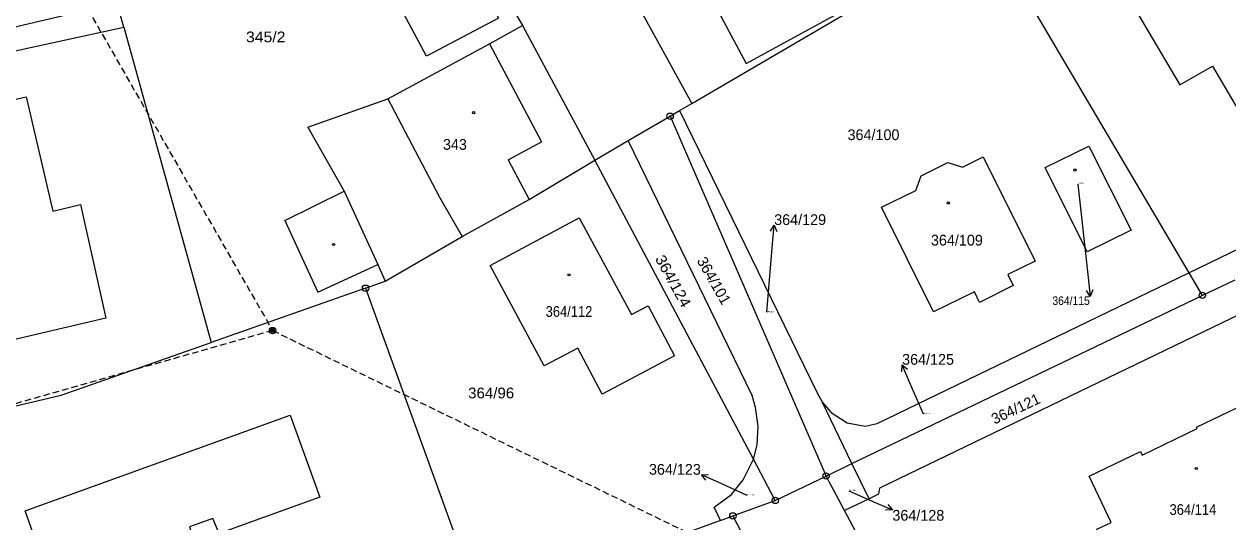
# Model space of a CAD drawing. Extents: x -592965 to -592390, y -1145071 to -1144631.
# Drawn here: x -592689.4 to -592594.1, y -1144977 to -1144937.6 of the extents above; entities that cross this region are included whole.
import ezdxf

# ---------------------------------------------------------------- set-up
doc = ezdxf.new("R2010")
doc.units = 0
doc.header["$LTSCALE"] = 0.17
doc.linetypes.add('MEDIUM_DASHED', pattern=[4.5, 3, -1.5])
doc.layers.add('4', color=7, linetype='Continuous', lineweight=25)

msp = doc.modelspace()

# ---------------------------------------------------------------- linework, layer by layer
at = {"layer": '4'}
for p, q in [((-592657.03, -1144925.29), (-592649.94, -1144937.68)), ((-592636.52, -1144943.86), (-592613.14, -1144930.18)), ((-592643.64, -1144930.93), (-592636.52, -1144943.86)), ((-592681.5, -1144937.82), (-592674.57, -1144962.77)), ((-592652.54, -1144939.13), (-592649.94, -1144937.68)), ((-592649.94, -1144937.68), (-592644.2, -1144948.33)), ((-592660.6, -1144943.48), (-592652.54, -1144939.13)), ((-592666.92, -1144945.72), (-592660.6, -1144943.48)), ((-592638.24, -1144944.86), (-592625.89, -1144973.34)), ((-592666.92, -1144945.72), (-592664.06, -1144950.8)), ((-592668.76, -1144953.11), (-592664.06, -1144950.8)), ((-592668.76, -1144953.11), (-592666.13, -1144958.79)), ((-592666.13, -1144958.79), (-592661.38, -1144956.59)), ((-592661.38, -1144956.59), (-592660.8, -1144957.92)), ((-592596.1, -1144959.04), (-592593.51, -1144957.8)), ((-592662.36, -1144958.47), (-592674.57, -1144962.77)), ((-592662.36, -1144958.47), (-592660.8, -1144957.92)), ((-592662.36, -1144958.47), (-592653.19, -1144983.74)), ((-592686.45, -1144966.95), (-592674.57, -1144962.77)), ((-592703.18, -1144970.84), (-592686.45, -1144966.95)), ((-592629.91, -1144975.27), (-592625.89, -1144973.34)), ((-592633.27, -1144976.49), (-592629.91, -1144975.27)), ((-592634.25, -1144976.85), (-592649.43, -1144982.37)), ((-592634.25, -1144976.85), (-592633.27, -1144976.49)), ((-592618.23, -1145004.75), (-592633.27, -1144976.49))]:
    msp.add_line(p, q, dxfattribs=at)
at = {"layer": '4', "lineweight": 13}
for p, q in [((-592636.53, -1144932.59), (-592632.22, -1144940.68)), ((-592632.22, -1144940.68), (-592624.61, -1144936.54)), ((-592652.54, -1144939.13), (-592648.42, -1144946.9)), ((-592660.6, -1144943.48), (-592656.51, -1144951.26)), ((-592651.07, -1144948.31), (-592648.42, -1144946.9)), ((-592651.07, -1144948.31), (-592649.4, -1144951.44)), ((-592664.06, -1144950.8), (-592661.38, -1144956.59)), ((-592656.51, -1144951.26), (-592654.71, -1144954.39))]:
    msp.add_line(p, q, dxfattribs=at)
at = {"layer": '4', "linetype": 'MEDIUM_DASHED'}
for points in [[(-592857.7, -1144647.96), (-592827.25, -1144698.04), (-592798.73, -1144745.3), (-592765.1, -1144800.74), (-592721.92, -1144873.86), (-592693.51, -1144920.47), (-592669.72, -1144961.82), (-592709.34, -1144973.09), (-592761.29, -1144989.89), (-592825.83, -1145034.08), (-592878.88, -1145071.17)], [(-592669.72, -1144961.82), (-592599.07, -1144996.19), (-592537.81, -1145025.68), (-592483.65, -1145051.69)]]:
    msp.add_lwpolyline(points, dxfattribs=at)
at = {"layer": '4'}
for points in [[(-592601.13, -1144936.9), (-592597.88, -1144942.39), (-592595.3, -1144940.9), (-592592.02, -1144946.46), (-592584.34, -1144941.94), (-592587.57, -1144936.44), (-592582.29, -1144933.34), (-592585.64, -1144927.65)], [(-592661.27, -1144933.1), (-592655.56, -1144930.04), (-592651.84, -1144937.11), (-592657.53, -1144940.1)], [(-592682.91, -1144960.84), (-592695.32, -1144963.74), (-592697.38, -1144954.72), (-592695.57, -1144954.34), (-592697.68, -1144945.28), (-592689.24, -1144943.33), (-592687.12, -1144952.37), (-592684.94, -1144951.85)], [(-592601.74, -1144953.89), (-592605.21, -1144955.59), (-592608.54, -1144948.93), (-592605.08, -1144947.23)], [(-592621.5, -1144952.06), (-592618.78, -1144950.73), (-592618.37, -1144949.58), (-592616.25, -1144948.52), (-592615.1, -1144948.89), (-592613.45, -1144948.07), (-592609.34, -1144956.33), (-592611.5, -1144957.4), (-592611.08, -1144958.26), (-592613.74, -1144959.6), (-592614.15, -1144958.75), (-592617.38, -1144960.33)], [(-592652.49, -1144956.68), (-592645.43, -1144952.89), (-592641.31, -1144960.55), (-592639.98, -1144959.87), (-592637.9, -1144963.82), (-592643.62, -1144966.87), (-592645.54, -1144963.21), (-592648.21, -1144964.61)], [(-592601.78, -1144983.1), (-592604.44, -1144977.55), (-592603.32, -1144977.01), (-592605.06, -1144973.35), (-592601, -1144971.39), (-592600.86, -1144971.68), (-592596.51, -1144969.57), (-592596.55, -1144969.48), (-592592.72, -1144967.63), (-592588.6, -1144976.22), (-592592.06, -1144977.86), (-592590.98, -1144980.12), (-592596.32, -1144982.68), (-592596.19, -1144982.99), (-592599.54, -1144984.65), (-592600.66, -1144982.55)], [(-592689.32, -1144976.1), (-592668.32, -1144968.52), (-592665.99, -1144975.02), (-592673.94, -1144977.88), (-592674.44, -1144976.7), (-592676.29, -1144977.37), (-592673.71, -1144984.65), (-592681.27, -1144987.36), (-592683.04, -1144982.4), (-592686.63, -1144983.68)]]:
    msp.add_lwpolyline(points, close=True, dxfattribs=at)
for points in [[(-592613.14, -1144930.18), (-592597.16, -1144957.25), (-592596.1, -1144959.04)], [(-592709.85, -1144942.41), (-592686.06, -1144936.85), (-592682.2, -1144935.31)], [(-592709.5, -1144943.92), (-592681.5, -1144937.82), (-592682.2, -1144935.31)], [(-592637.49, -1144944.42), (-592626.62, -1144966.7), (-592626.18, -1144967.53), (-592625.48, -1144968.32), (-592624.23, -1144969.12), (-592622.8, -1144969.4), (-592621.85, -1144969.17), (-592597.16, -1144957.25), (-592570.98, -1144944.6), (-592559.91, -1144939.25)], [(-592557.84, -1144942.95), (-592559.8, -1144944.02), (-592559.63, -1144944.38), (-592592.29, -1144960.13), (-592621.67, -1144974.31), (-592621.74, -1144974.77), (-592622.49, -1144975.13), (-592624.43, -1144976.07)], [(-592644.2, -1144948.33), (-592641.55, -1144946.78), (-592638.24, -1144944.86), (-592637.49, -1144944.42), (-592636.52, -1144943.86)], [(-592634.25, -1144976.85), (-592634.75, -1144975.81), (-592633.39, -1144974.79), (-592632.45, -1144973.64), (-592631.65, -1144972), (-592631.35, -1144970.88), (-592631.28, -1144969.38), (-592631.48, -1144967.91), (-592631.74, -1144966.96), (-592641.55, -1144946.78)], [(-592660.8, -1144957.92), (-592654.71, -1144954.39), (-592649.4, -1144951.44), (-592644.2, -1144948.33)], [(-592629.91, -1144975.27), (-592631.65, -1144972), (-592644.2, -1144948.33)], [(-592625.89, -1144973.34), (-592623.84, -1144972.35), (-592596.1, -1144959.04)], [(-592622.49, -1144975.13), (-592623.84, -1144972.35), (-592626.18, -1144967.53)], [(-592625.89, -1144973.34), (-592625.69, -1144973.71), (-592624.75, -1144975.48)], [(-592611.32, -1145000.71), (-592624.43, -1144976.07), (-592624.75, -1144975.48)]]:
    msp.add_lwpolyline(points, dxfattribs=at)
at = {"layer": '4', "lineweight": 13}
for points in [[(-592605.95, -1144950.23), (-592605.134, -1144957.629), (-592604.97, -1144959.12)], [(-592630.57, -1144960.37), (-592630.124, -1144954.965), (-592630.001, -1144953.47)], [(-592630.291, -1144953.948), (-592630.001, -1144953.47), (-592629.793, -1144953.989)], [(-592604.776, -1144958.596), (-592604.97, -1144959.12), (-592605.273, -1144958.65)], [(-592619.901, -1144965.088), (-592619.871, -1144964.53), (-592619.443, -1144964.888)], [(-592618.17, -1144968.44), (-592619.273, -1144965.905), (-592619.871, -1144964.53)], [(-592635.408, -1144973.669), (-592635.76, -1144973.235), (-592635.202, -1144973.214)], [(-592632.15, -1144974.87), (-592634.394, -1144973.854), (-592635.76, -1144973.235)], [(-592624.08, -1144974.52), (-592622.015, -1144975.42), (-592620.64, -1144976.02)], [(-592620.998, -1144975.591), (-592620.64, -1144976.02), (-592621.198, -1144976.049)]]:
    msp.add_lwpolyline(points, dxfattribs=at)
at = {"layer": '4'}
for centre, radius in [((-592653.79, -1144944.58), 0.0875), ((-592638.24, -1144944.86), 0.25), ((-592638.24, -1144944.86), 0.0164), ((-592606.18, -1144949.12), 0.0875), ((-592616.22, -1144951.72), 0.0875), ((-592664.89, -1144955.01), 0.0875), ((-592646.25, -1144957.41), 0.0875), ((-592662.36, -1144958.47), 0.25), ((-592662.36, -1144958.47), 0.0164), ((-592596.1, -1144959.04), 0.25), ((-592596.1, -1144959.04), 0.0164), ((-592669.72, -1144961.82), 0.25), ((-592669.72, -1144961.82), 0.25), ((-592669.72, -1144961.82), 0.15), ((-592669.72, -1144961.82), 0.15), ((-592669.72, -1144961.82), 0.075), ((-592669.72, -1144961.82), 0.075), ((-592625.89, -1144973.34), 0.25), ((-592596.58, -1144972.74), 0.0875), ((-592625.89, -1144973.34), 0.0164), ((-592629.91, -1144975.27), 0.25), ((-592629.91, -1144975.27), 0.0164), ((-592633.27, -1144976.49), 0.25), ((-592633.27, -1144976.49), 0.0164)]:
    msp.add_circle(centre, radius, dxfattribs=at)

# ---------------------------------------------------------------- texts
for s, height, width, p in [('345/2', 0.85, 1.1, (-592671.826, -1144939.01)), ('364/115', 0.68, 0.9, (-592607.97, -1144959.8)), ('364/112', 0.85, 0.9, (-592648.097, -1144960.74)), ('364/129', 0.1, 1.1, (-592630.57, -1144960.37)), ('364/96', 0.85, 1.05, (-592654.237, -1144967.19)), ('364/125', 0.1, 1.15, (-592618.17, -1144968.44)), ('364/123', 0.1, 1.15, (-592632.15, -1144974.87)), ('364/128', 0.1, 1.1, (-592624.08, -1144974.52)), ('364/114', 0.85, 0.9, (-592598.694, -1144976.415))]:
    msp.add_text(s, height=height, dxfattribs=dict(at, width=width)).set_placement(p)
for s, height, p in [('364/100', 0.85, (-592624.191, -1144946.75)), ('343', 0.85, (-592656.23, -1144947.52)), ('364/115', 0.1, (-592605.95, -1144950.23)), ('364/129', 0.85, (-592630, -1144953.47)), ('364/109', 0.85, (-592617.589, -1144955.095)), ('364/125', 0.85, (-592619.871, -1144964.53)), ('364/123', 0.85, (-592639.917, -1144973.235)), ('364/128', 0.85, (-592620.64, -1144976.87))]:
    msp.add_text(s, height=height, dxfattribs=at).set_placement(p)
at = {"layer": '4', "width": 1.1}
msp.add_text('364/124', height=0.85, rotation=298.8, dxfattribs=at).set_placement((-592639.463, -1144956.132))
at = {"layer": '4'}
for s, rotation, p in [('364/101', 299.725, (-592636.155, -1144956.3)), ('364/121', 25.2, (-592612.557, -1144969.273))]:
    msp.add_text(s, height=0.85, rotation=rotation, dxfattribs=at).set_placement(p)

doc.saveas('drawing.dxf')
